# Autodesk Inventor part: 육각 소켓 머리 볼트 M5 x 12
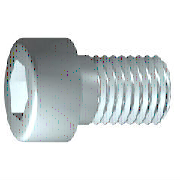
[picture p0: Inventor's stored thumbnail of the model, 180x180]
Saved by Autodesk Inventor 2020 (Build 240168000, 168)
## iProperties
IsCustomPart: 1
Created: 2012-02
Part Number: 육각 소켓 머리 볼트 M5 x 12
Material: 스테인리스강
Description: 6각 소켓 머리 캡 나사
Document SubType Name: Modeling
Standard: ISO 4762
Designer: mdu-01
Standard Revision: Fourth edition 2004-03-01
Standards Organization: ISO
Language: ko-KR
Size Designation: M5 x 12
Categories: <MemberInstance><Categories><Category DisplayName="조임쇠" InternalName="e4da775c-781d-43d5-af7c-5136215cf5a6" Mnemonic="FSTN"><Category DisplayName="볼트" InternalN
Density: 7.75 g/cm^3
Appearance: 반광택
Author: mdu-01
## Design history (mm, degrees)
sketch "스케치1"
  geometry: L1 (-1.167, 0)-(12, 0); L2 (12, 0)-(12, 2.5); L3 (12, 2.5)-(2, 2.5); L4 (2, 2.5)-(1.509, 2.5); L5 (1.509, 2.5)-(0, 2.5); L6 (0, 2.5)-(0, 4.25); L7 (0, 4.25)-(-5, 4.25); L8 (-5, 4.25)-(-5, 2.309); L9 (-5, 2.309)-(-2.5, 2.309); L10 (-2.5, 2.309)-(-1.167, 0); L11 (-8.4, 0)-(15.4, 0) reference; L12 (0, -0.85)-(0, 5.1) reference; L13 (2, 2.5)-(0, 2.5)
  constraints: 22 end point, 6 parallel, 2 collinear, 2 perpendicular, 1 horizontal, 1 point on line
  dimensions: "d1" = 10 distance from line of L3.end L2 (= GEL); "d2" = 0.49086 distance of L4.end L3.end (computed from GAL); "d3" = 5 distance between parallel lines of L8 L6 (= KOH); "d4" = 2.5 distance of L8.end L9.end (= INTI); "d5" = 60 deg angle of L10 L1; "d6" = 5 diameter of L3 L1 (= GD); "d7" = 5 diameter of L5 L1 (= BDM); "d8" = 4.6188 diameter of L9 L1 (= 1.1547 x SW); "d9" = 8.5 diameter of L7 L1 (= KOD); "d26" = 12 distance between parallel lines of L12 L2 (= NLG)
revolve "본체" sketch "스케치1" stored, may be unused: angle "d10" = 90 deg
sketch "스케치2"
  geometry: L1 (0, -5.95)-(0, 5.95) reference; L2 (-5.95, 0)-(5.95, 0) reference; L3 (2.309, 0)-(1.155, -2); L4 (1.155, -2)-(-1.155, -2); L5 (-1.155, -2)-(-2.309, 0); L6 (-2.309, 0)-(-1.155, 2); L7 (-1.155, 2)-(1.155, 2); L8 (1.155, 2)-(2.309, 0); 2 further points
  constraints: 12 end point, 1 coincident, 1 horizontal alignment, 1 point on line, 12 other
extrude "슬롯" join sketch "스케치2" stored distance "d11" = 10; taper "d12" = 0 deg
workplane "Work Plane1"
fillet "Fillet2" dims "d30" = 0.05 (= R)
body "Solid1"
fillet "모깎기1" dims "d17" = 0.5 (= RR)
feature "스레드" dims "d13" = 10 (= GEL), "d14" = 0
chamfer "모따기1" distance "d15" = 0.49076 (= -0.5 x SPD + 0.5 x GD); stored, may be unused: second distance "d16" = 0.49076 (= GUL), angle "d27" = 45 deg
other parameters: "GD" = 5 [user parameter; used in 2 equation terms], "NLG" = 12 [user parameter; used in 1 equation term], "GEL" = 10 [user parameter; used in 2 equation terms], "KOD" = 8.5 [user parameter; used in 1 equation term], "KOH" = 5 [user parameter; used in 1 equation term], "INTI" = 2.5 [user parameter; used in 1 equation term], "GAL" = 0.49076 (= 0.61345 x PTC) [user parameter; used in 1 equation term], "GUL" = 0.49076 (= 0.61345 x PTC) [user parameter; used in 1 equation term], "BDM" = 5 (= NND) [user parameter; used in 1 equation term], "SW" = 4 [user parameter; used in 2 equation terms], "RR" = 0.5 [user parameter; used in 1 equation term], "SPD" = 4.01848 (= NND - 1.2269 x PTC) [user parameter; used in 1 equation term], "d19" = 0, "d28" = 0, "d29" = 0, "R" = 0.05 [user parameter; used in 1 equation term], "TOA" = 30 deg [user parameter], "GD1" = 4.01848 (= THREADDIA - 1.2269 x PTC) [user parameter], "THREADDIA" = 5 [user parameter; used in 1 equation term], "FAWI" = 45 deg [user parameter], "TPU" = 12.5 (computed from PTC) [user parameter], "PTC" = 0.8 [user parameter; used in 5 equation terms], "NND" = 5 [user parameter; used in 2 equation terms], "E0" = 4.62 (= 1.155 x SW) [user parameter]
